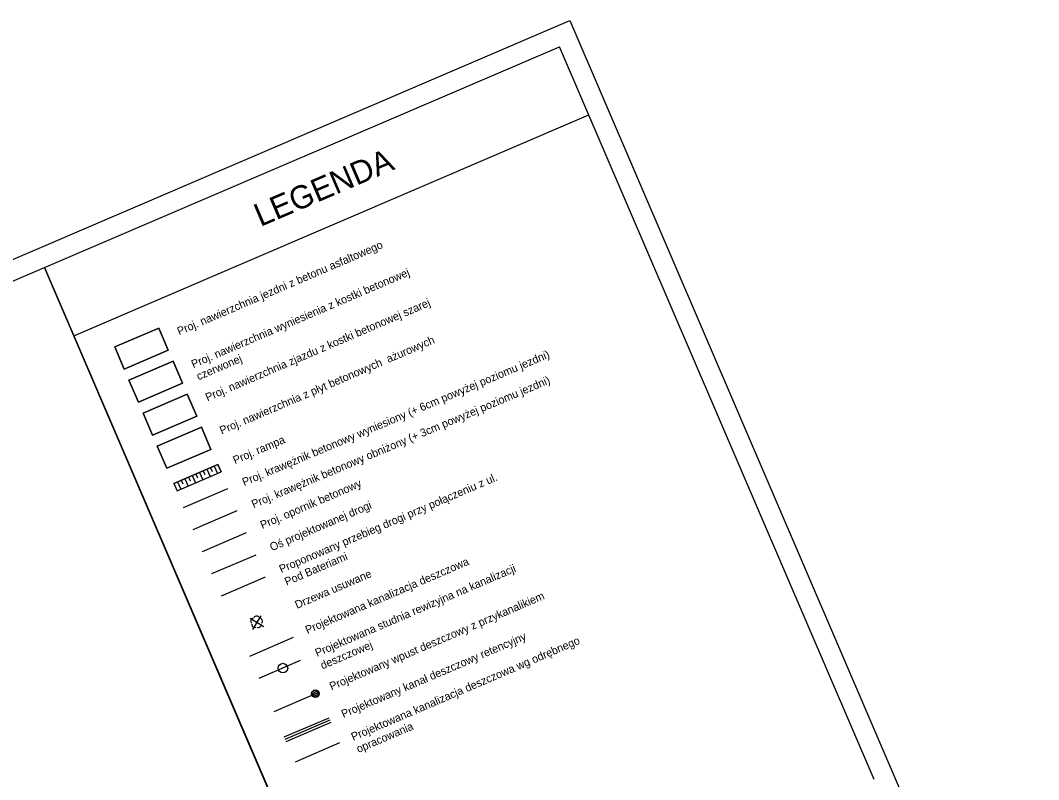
# Model space of a CAD drawing. Extents: x 7500108 to 7500715, y 5768804 to 5769157.
# Drawn here: x 7500544.2 to 7500671.4, y 5769062.2 to 5769157.1 of the extents above; entities that cross this region are included whole.
import ezdxf

# ---------------------------------------------------------------- set-up
doc = ezdxf.new("R2010")
doc.units = 0
for name, color, linetype in [('1_proj_kd_etap1', 7, 'Continuous'), ('1_proj_KD_etap3', 7, 'Continuous'), ('2_opisy_etap3', 7, 'Continuous'), ('2_uwagi_MM', 7, 'Continuous'), ('4724_KANALIZACJA_OS_PRZEWODU_PR', 7, 'Continuous'), ('_HA_Utwardzenie terenu', 7, 'Continuous'), ('BUDYNKI', 7, 'Continuous'), ('CMENTARZE_I_POMNIKI', 7, 'Continuous'), ('DZIALKI', 7, 'Continuous'), ('EG_PROJEKTY', 7, 'Continuous'), ('ELEMENTY_BUDYNKOW', 7, 'Continuous'), ('EWIDENCJA', 7, 'Continuous'), ('KLASOUZYTKI', 7, 'Continuous'), ('OGRODZENIA', 7, 'Continuous'), ('opis_osi', 7, 'Continuous'), ('SYSTEM', 7, 'Continuous'), ('TEKSTY', 7, 'Continuous'), ('UZ_KANALIZACJA', 7, 'Continuous'), ('UZ_SPECJALNE', 7, 'Continuous'), ('UZYTKI', 7, 'Continuous')]:
    doc.layers.add(name, color=color, linetype=linetype)

# ---------------------------------------------------------------- blocks, each defined once
blk = doc.blocks.new('1422')
at = {"layer": 'UZ_SPECJALNE'}
blk.add_circle((0, 0), 0.1, dxfattribs=at)
for centre, start, end in [((-0.71, 0.23), 102.5, 221.75), ((0, 0.75), 30.19, 149.77), ((0.71, 0.23), 318.3, 77.49), ((-0.44, -0.61), 174.33, 293.45), ((0.44, -0.61), 246.24, 5.74)]:
    blk.add_arc(centre, 0.75, start, end, dxfattribs=at)

msp = doc.modelspace()

# ---------------------------------------------------------------- linework, layer by layer
at = {"layer": '1_proj_kd_etap1'}
for p, q in [((7500578.26, 5769079.98), (7500572.81, 5769077.61)), ((7500579.16, 5769077.1), (7500573.98, 5769074.85)), ((7500581.05, 5769072.95), (7500575.86, 5769070.7)), ((7500577.16, 5769067.55), (7500582.79, 5769069.95)), ((7500577.29, 5769067.28), (7500582.9, 5769069.67)), ((7500577.4, 5769067), (7500583.04, 5769069.41))]:
    msp.add_line(p, q, dxfattribs=at)
msp.add_circle((7500576.99, 5769076.15), 0.6, dxfattribs=at)
at = {"layer": '1_proj_KD_etap3'}
msp.add_lwpolyline([(7500603.81, 5768994.34), (7500172.11, 5768809.11), (7500115.53, 5768940.99), (7500547.22, 5769126.21)], close=True, dxfattribs=at)
at = {"layer": '2_opisy_etap3'}
msp.add_lwpolyline([(7500558.94, 5769109.39), (7500564.45, 5769111.76), (7500563.27, 5769114.52), (7500557.75, 5769112.15), (7500558.94, 5769109.39)], dxfattribs=at)
at = {"layer": '2_uwagi_MM'}
msp.add_line((7500568.13, 5769087.96), (7500573.65, 5769090.32), dxfattribs=at)
at = {"layer": '4724_KANALIZACJA_OS_PRZEWODU_PR'}
msp.add_line((7500584.08, 5769066.81), (7500578.54, 5769064.41), dxfattribs=at)
at = {"layer": '_HA_Utwardzenie terenu'}
msp.add_lwpolyline([(7500562.48, 5769101.12), (7500568, 5769103.49), (7500566.82, 5769106.25), (7500561.3, 5769103.88), (7500562.48, 5769101.12)], dxfattribs=at)
at = {"layer": 'BUDYNKI'}
for p, q in [((7500566.58, 5769100.61), (7500566.97, 5769099.69)), ((7500567.04, 5769100.81), (7500567.24, 5769100.35)), ((7500567.5, 5769101), (7500567.89, 5769100.08)), ((7500567.96, 5769101.2), (7500568.16, 5769100.74)), ((7500568.42, 5769101.4), (7500568.81, 5769100.48)), ((7500563.82, 5769099.43), (7500564.22, 5769098.51)), ((7500564.28, 5769099.62), (7500564.48, 5769099.16)), ((7500564.74, 5769099.82), (7500565.14, 5769098.9)), ((7500565.2, 5769100.02), (7500565.4, 5769099.56)), ((7500565.66, 5769100.21), (7500566.06, 5769099.3)), ((7500566.12, 5769100.41), (7500566.32, 5769099.95))]:
    msp.add_line(p, q, dxfattribs=at)
at = {"layer": 'CMENTARZE_I_POMNIKI'}
msp.add_lwpolyline([(7500144.97, 5768872.37), (7500115.53, 5768940.99), (7500547.22, 5769126.21), (7500566.93, 5769080.29), (7500577.05, 5769056.69), (7500603.81, 5768994.34), (7500172.11, 5768809.11), (7500169.25, 5768815.79)], close=True, dxfattribs=at)
at = {"layer": 'DZIALKI'}
for points in [[(7500108.06, 5768940.5), (7500612.86, 5769157.1), (7500671.42, 5769020.63), (7500166.62, 5768804.03)], [(7500115.01, 5768940.77), (7500547.22, 5769126.21), (7500550.88, 5769117.68), (7500586.52, 5769034.61), (7500603.81, 5768994.34), (7500171.6, 5768808.89)]]:
    msp.add_lwpolyline(points, close=True, dxfattribs=at)
at = {"layer": 'ELEMENTY_BUDYNKOW'}
for p, q in [((7500568.88, 5769101.59), (7500563.36, 5769099.23)), ((7500563.76, 5769098.31), (7500569.27, 5769100.68)), ((7500569.27, 5769100.68), (7500568.88, 5769101.59)), ((7500563.36, 5769099.23), (7500563.76, 5769098.31))]:
    msp.add_line(p, q, dxfattribs=at)
at = {"layer": 'EWIDENCJA'}
msp.add_line((7500565.77, 5769093.47), (7500571.28, 5769095.84), dxfattribs=at)
at = {"layer": 'KLASOUZYTKI'}
for p, q in [((7500547.22, 5769126.21), (7500611.55, 5769153.81)), ((7500650.85, 5769062.22), (7500611.55, 5769153.81)), ((7500550.88, 5769117.68), (7500615.21, 5769145.28)), ((7500586.52, 5769034.61), (7500547.22, 5769126.21))]:
    msp.add_line(p, q, dxfattribs=at)
at = {"layer": 'OGRODZENIA'}
msp.add_lwpolyline([(7500560.71, 5769105.26), (7500566.22, 5769107.62), (7500565.04, 5769110.38), (7500559.53, 5769108.02), (7500560.71, 5769105.26)], dxfattribs=at)
at = {"layer": 'opis_osi'}
for p, q in [((7500580.67, 5769073), (7500581.26, 5769073.26)), ((7500580.75, 5769072.82), (7500581.34, 5769073.08)), ((7500580.83, 5769072.64), (7500581.42, 5769072.9))]:
    msp.add_line(p, q, dxfattribs=at)
msp.add_lwpolyline([(7500580.91, 5769072.46), (7500580.59, 5769073.19), (7500581.18, 5769073.44), (7500581.5, 5769072.72)], close=True, dxfattribs=at)
msp.add_circle((7500581.05, 5769072.95), 0.473, dxfattribs=at)
at = {"layer": 'SYSTEM'}
for p, q in [((7500566.95, 5769090.71), (7500572.46, 5769093.08)), ((7500574.61, 5769081.31), (7500572.9, 5769082.34)), ((7500573.24, 5769080.97), (7500574.27, 5769082.68))]:
    msp.add_line(p, q, dxfattribs=at)
at = {"layer": 'TEKSTY'}
for p, q in [((7500564.59, 5769096.23), (7500570.1, 5769098.59)), ((7500569.32, 5769085.2), (7500574.83, 5769087.56))]:
    msp.add_line(p, q, dxfattribs=at)
at = {"layer": 'UZ_KANALIZACJA'}
msp.add_lwpolyline([(7500557.16, 5769113.53), (7500562.67, 5769115.9), (7500561.49, 5769118.65), (7500555.98, 5769116.29), (7500557.16, 5769113.53)], dxfattribs=at)
at = {"layer": 'UZYTKI'}
for p, q in [((7500563.36, 5769099.23), (7500568.88, 5769101.59)), ((7500563.76, 5769098.31), (7500569.27, 5769100.68)), ((7500568.88, 5769101.59), (7500569.27, 5769100.68)), ((7500563.36, 5769099.23), (7500563.76, 5769098.31))]:
    msp.add_line(p, q, dxfattribs=at)
for points in [[(7500555.98, 5769116.29), (7500561.49, 5769118.65), (7500562.67, 5769115.9), (7500557.16, 5769113.53)], [(7500557.75, 5769112.15), (7500563.27, 5769114.52), (7500564.45, 5769111.76), (7500558.94, 5769109.39)], [(7500559.53, 5769108.02), (7500565.04, 5769110.38), (7500566.22, 5769107.62), (7500560.71, 5769105.26)], [(7500561.3, 5769103.88), (7500566.82, 5769106.25), (7500568, 5769103.49), (7500562.48, 5769101.12)]]:
    msp.add_lwpolyline(points, close=True, dxfattribs=at)

# ---------------------------------------------------------------- block references
at = {"layer": 'UZ_SPECJALNE', "xscale": 0.49999999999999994, "yscale": 0.49999999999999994, "rotation": 9.777489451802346e-09}
msp.add_blockref('1422', (7500573.7, 5769081.91), dxfattribs=at)

# ---------------------------------------------------------------- texts
at = {"layer": 'EG_PROJEKTY'}
for s, rotation, p in [('Proj. nawierzchnia jezdni z betonu asfaltowego', 23.2227, (7500564.03, 5769117.73)), ('Proj. nawierzchnia wyniesienia z kostki betonowej ', 23.2227, (7500565.8, 5769113.62)), ('Proj. nawierzchnia zjazdu z kostki betonowej szarej', 23.2227, (7500567.57, 5769109.48)), ('Proj. nawierzchnia z płyt betonowych  ażurowych ', 23.2227, (7500569.35, 5769105.34)), ('czerwonej', 23.2227, (7500566.45, 5769112.1)), ('Proj. krawężnik betonowy wyniesiony (+ 6cm powyżej poziomu jezdni)', 22.8238, (7500572.16, 5769098.89)), ('Proj. krawężnik betonowy obniżony (+ 3cm powyżej poziomu jezdni)', 22.8238, (7500573.32, 5769096.13)), ('Proj. rampa', 23.2227, (7500571.01, 5769101.62)), ('Proj. opornik betonowy ', 23.2227, (7500574.42, 5769093.52)), ('Proponowany przebieg drogi przy połączeniu z ul. ', 23.2227, (7500576.78, 5769088.01)), ('Oś projektowanej drogi', 23.2227, (7500575.61, 5769090.76)), ('Pod Bateriami', 23.2227, (7500577.46, 5769086.44)), ('Projektowana kanalizacja deszczowa', 23.2227, (7500580.05, 5769080.41)), ('Projektowana studnia rewizyjna na kanalizacji ', 23.2227, (7500581.27, 5769077.55)), ('Drzewa usuwane', 23.2227, (7500578.75, 5769083.55)), ('Projektowany wpust deszczowy z przykanalikiem', 23.2227, (7500583.07, 5769073.36)), ('Projektowany kanał deszczowy retencyjny', 23.2227, (7500584.55, 5769069.91)), ('deszczowej', 23.2227, (7500581.94, 5769075.98)), ('Projektowana kanalizacja deszczowa wg odrębnego ', 23.2227, (7500585.78, 5769067.05)), ('opracowania', 23.2227, (7500586.43, 5769065.54))]:
    msp.add_text(s, height=1, rotation=rotation, dxfattribs=at).set_placement(p)
at = {"layer": 'KLASOUZYTKI'}
msp.add_text('LEGENDA', height=2.88, rotation=23.2227, dxfattribs=at).set_placement((7500574.18, 5769131.27))

doc.saveas('drawing.dxf')
